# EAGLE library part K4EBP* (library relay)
UNIQUELY DESIGNED RELAY NAiS Source: http://www.mew-europe.com/.. en_ds_61013_0000.pdf
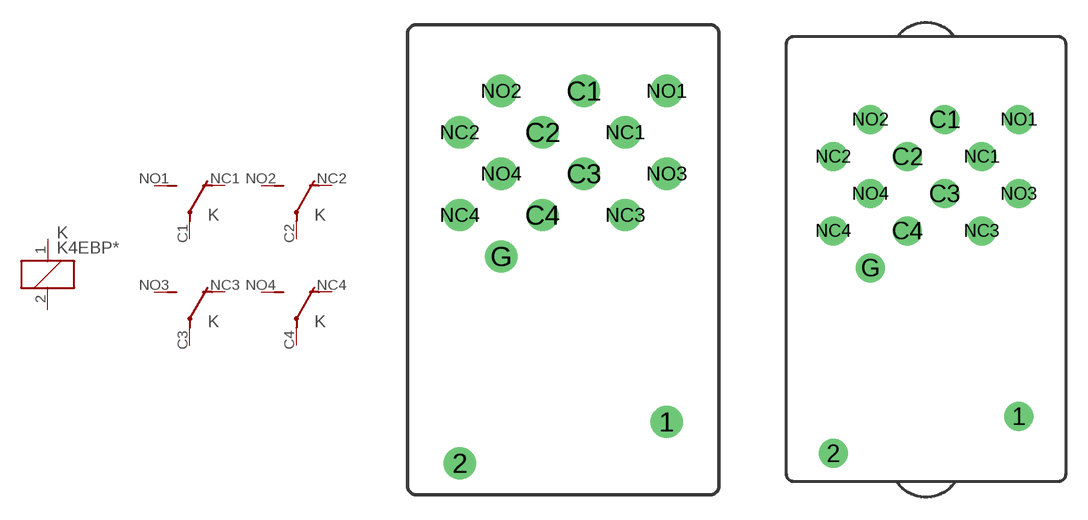
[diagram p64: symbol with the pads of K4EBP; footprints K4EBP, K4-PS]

Designator prefix K; gates _=K 1=U 2=U 3=U 4=U

## K4EBP-3V-1 (OC_FARNELL: unknown; OC_NEWARK: unknown), K4EBP-6V-1 (OC_FARNELL: unknown; OC_NEWARK: unknown), K4EBP-12V-1 (OC_FARNELL: unknown; OC_NEWARK: unknown), K4EBP-24V-1 (OC_FARNELL: unknown; OC_NEWARK: unknown), K4EBP-28V-1 (OC_FARNELL: unknown; OC_NEWARK: unknown), K4EBP-48V-1 (OC_FARNELL: unknown; OC_NEWARK: unknown), K4EBP-110V-1 (OC_FARNELL: unknown; OC_NEWARK: unknown)  [K4EBP]
1  _:1  pas
2  _:2  pas
C1  1:P  pas
C2  2:P  pas
C3  3:P  pas
C4  4:P  pas
NC1  1:O  pas
NC2  2:O  pas
NC3  3:O  pas
NC4  4:O  pas
NO1  1:S  pas
NO2  2:S  pas
NO3  3:S  pas
NO4  4:S  pas

## K4EBPS (OC_FARNELL: unknown; OC_NEWARK: unknown)  [K4-PS]
Pads as for K4EBP

## Footprint K4EBP (pad centres in mm)
UNIQUELY DESIGNED RELAY NAiS Source: http://www.mew-europe.com/.. en_ds_61013_0000.pdf
drill 1.3 round: 1 6.25,-6.25; 2 -6.25,-8.75; C1 1.25,13.75; C2 -1.25,11.25; C3 1.25,8.75; C4 -1.25,6.25; G -3.75,3.75; NC1 3.75,11.25; NC2 -6.25,11.25; NC3 3.75,6.25; NC4 -6.25,6.25; NO1 6.25,13.75; NO2 -3.75,13.75; NO3 6.25,8.75; NO4 -3.75,8.75

## Footprint K4-PS (pad centres in mm)
RELAY Socked NAiS Source: http://www.mew-europe.com/.. en_ds_61013_0000.pdf
drill 1.3 round: 1 6.25,-6.25; 2 -6.25,-8.75; C1 1.25,13.75; C2 -1.25,11.25; C3 1.25,8.75; C4 -1.25,6.25; G -3.75,3.75; NC1 3.75,11.25; NC2 -6.25,11.25; NC3 3.75,6.25; NC4 -6.25,6.25; NO1 6.25,13.75; NO2 -3.75,13.75; NO3 6.25,8.75; NO4 -3.75,8.75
